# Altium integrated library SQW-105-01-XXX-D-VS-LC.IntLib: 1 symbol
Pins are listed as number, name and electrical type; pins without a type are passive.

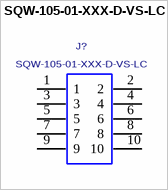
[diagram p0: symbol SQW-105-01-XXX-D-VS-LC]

## SQW-105-01-XXX-D-VS-LC
designator J?
Socket Strip, Dual Row, Surface Mount, 2mm Pitch, 10 Pins.; MANUFACTURER: SAMTEC
footprint SQW-105-01-XXX-D-VS-LC
pins: 1, 2, 3, 4, 5, 6, 7, 8, 9, 10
